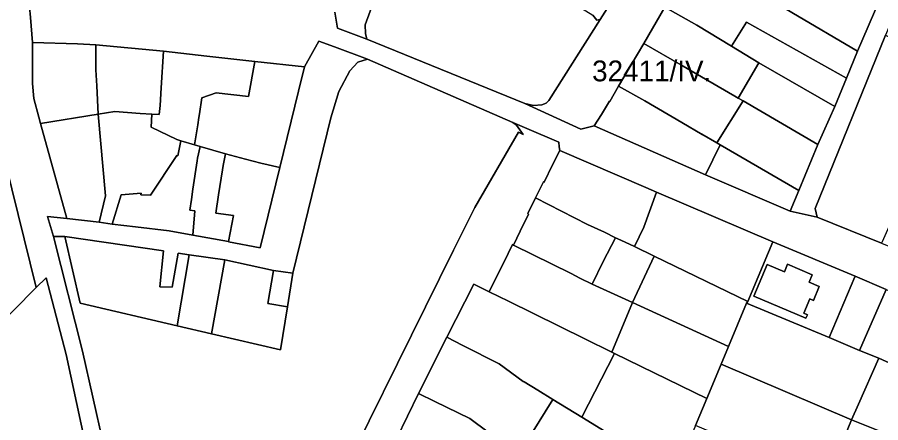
# Model space of a CAD drawing. Extents: x -545779 to -541342, y -1153413 to -1149956.
# Drawn here: x -544066.7 to -543859.4, y -1151540.7 to -1151443.3 of the extents above; entities that cross this region are included whole.
import ezdxf

# ---------------------------------------------------------------- set-up
doc = ezdxf.new("R2010")
doc.units = 0
for name, color, linetype in [('95590013', 7, 'Continuous'), ('95640013', 7, 'Continuous'), ('95660013', 7, 'Continuous')]:
    doc.layers.add(name, color=color, linetype=linetype)

msp = doc.modelspace()

# ---------------------------------------------------------------- linework, layer by layer
at = {"layer": '95590013'}
for points in [[(-543864.92, -1151451.44), (-543880.7, -1151442.14), (-543882.45, -1151441.11), (-543879.44, -1151435.98), (-543880.89, -1151435.09), (-543879.44, -1151432.74), (-543877.14, -1151429.03), (-543877.1, -1151429.06), (-543859.58, -1151438.92)], [(-543867.57, -1151457.91), (-543870.36, -1151464.7), (-543888.64, -1151454.25), (-543895.17, -1151450.23), (-543891.62, -1151444.46)], [(-543858.23, -1151447.61), (-543845.56, -1151454.17), (-543851.61, -1151466.63), (-543856.46, -1151476.49), (-543850.95, -1151479.09), (-543859.02, -1151497.28), (-543859.15, -1151497.57), (-543874.59, -1151491.33), (-543875.12, -1151489.24)], [(-543888.64, -1151454.25), (-543870.36, -1151464.7), (-543874.49, -1151473.89), (-543892.43, -1151463.38), (-543893.59, -1151462.7)], [(-543898.7, -1151473.44), (-543892.43, -1151463.38), (-543874.49, -1151473.89), (-543879.06, -1151484.91), (-543897.9, -1151473.91)], [(-544062.12, -1151508.24), (-544078.49, -1151524.76), (-544088.04, -1151515.33), (-544106.01, -1151497.58), (-544109.75, -1151501.5), (-544111.49, -1151503.24), (-544116.04, -1151498.64), (-544108.55, -1151493.23), (-544095.64, -1151483.9), (-544089.36, -1151479.12), (-544081.32, -1151473.35), (-544072.41, -1151466.98)], [(-544045.51, -1151486.18), (-544046.99, -1151492.53), (-544054.77, -1151491.65), (-544061.07, -1151468.84), (-544047.29, -1151466.58)], [(-543901.43, -1151481.18), (-543897.9, -1151473.91), (-543879.06, -1151484.91), (-543881.14, -1151489.91)], [(-543918.52, -1151498.37), (-543916.28, -1151493.68), (-543913.17, -1151485.27), (-543885.28, -1151497.22), (-543891.31, -1151511.55), (-543913.8, -1151500.66)], [(-543918.93, -1151511.86), (-543928.68, -1151507.38), (-543926.04, -1151501.94), (-543923.02, -1151496.25), (-543921.76, -1151496.84), (-543918.52, -1151498.37), (-543913.8, -1151500.66)], [(-543891.31, -1151511.55), (-543885.28, -1151497.22), (-543865.54, -1151505.52), (-543865.61, -1151505.69), (-543871.74, -1151520.26), (-543891.57, -1151511.95)], [(-543895.94, -1151522.41), (-543918.93, -1151511.86), (-543913.8, -1151500.66), (-543891.31, -1151511.55), (-543891.57, -1151511.95)], [(-543876.57, -1151506.93), (-543875.82, -1151505.2), (-543881.71, -1151502.65), (-543882.48, -1151504.43), (-543886.63, -1151502.71), (-543889.83, -1151510.27), (-543877.33, -1151515.58), (-543876.98, -1151514.76), (-543877.81, -1151514.41), (-543876.35, -1151510.96), (-543875.51, -1151511.31), (-543874.11, -1151508)], [(-543864.44, -1151523.32), (-543871.74, -1151520.26), (-543865.61, -1151505.69), (-543865.54, -1151505.52), (-543858.06, -1151508.67)], [(-543897.69, -1151526.61), (-543901.15, -1151534.9), (-543923.3, -1151524.04), (-543923.95, -1151523.73), (-543918.93, -1151511.86), (-543895.94, -1151522.41)], [(-543864.44, -1151523.32), (-543859.86, -1151525.24), (-543864.71, -1151536.29), (-543866.35, -1151540.03), (-543897.69, -1151526.61), (-543895.94, -1151522.41), (-543891.57, -1151511.95), (-543871.74, -1151520.26)], [(-543908.74, -1151553.12), (-543931.16, -1151539.37), (-543923.3, -1151524.04), (-543901.15, -1151534.9), (-543903.86, -1151541.41)], [(-543866.35, -1151540.03), (-543868.11, -1151544.31), (-543866.19, -1151545.1), (-543868.96, -1151552.11), (-543870.4, -1151555.33), (-543873.85, -1151554.05), (-543903.86, -1151541.41), (-543901.15, -1151534.9), (-543897.69, -1151526.61)], [(-543931.16, -1151539.37), (-543908.74, -1151553.12), (-543909.99, -1151556.12), (-543915.76, -1151570.84), (-543916.2, -1151571.83), (-543944.42, -1151550.28), (-543945.42, -1151549.52), (-543946.47, -1151548.7), (-543938.07, -1151535.13)]]:
    msp.add_lwpolyline(points, close=True, dxfattribs=at)
at = {"layer": '95640013'}
for points in [[(-543846.73, -1151420.31), (-543858.23, -1151447.61), (-543875.12, -1151489.24), (-543874.59, -1151491.33), (-543881.14, -1151489.91), (-543879.06, -1151484.91), (-543874.49, -1151473.89), (-543870.36, -1151464.7), (-543867.57, -1151457.91), (-543864.92, -1151451.44), (-543859.58, -1151438.92)], [(-543978.45, -1151432.12), (-543983.11, -1151445.08), (-543983.05, -1151447.16), (-543982.78, -1151448.51), (-543989.81, -1151445.87), (-543990.4, -1151442.09)], [(-543911.19, -1151440.86), (-543916.27, -1151449.57), (-543922.31, -1151459.86), (-543924.4, -1151463.5), (-543924.51, -1151463.43), (-543926.44, -1151466.65), (-543928.13, -1151469.39), (-543931.36, -1151470.13), (-543944.8, -1151463.97), (-543942.7, -1151464.52), (-543940.7, -1151464.35), (-543939.69, -1151463.92), (-543939.06, -1151463.27), (-543926.7, -1151443.82), (-543923.74, -1151439.11)], [(-543923.74, -1151439.11), (-543926.7, -1151443.82), (-543927.51, -1151443.98), (-543928.47, -1151442.75)], [(-544063.73, -1151440.78), (-544063.52, -1151443.31), (-544063.02, -1151449.37), (-544062.99, -1151459.16), (-544062.69, -1151462.83), (-544061.48, -1151467.29), (-544061.07, -1151468.84), (-544054.77, -1151491.65), (-544059.38, -1151491.13), (-544058, -1151496), (-544051.04, -1151523.5), (-544043.56, -1151556.66), (-544036.62, -1151600.3), (-544039.55, -1151601.25), (-544047.71, -1151557.78), (-544054.9, -1151524.32), (-544059.76, -1151505.86), (-544062.12, -1151508.24), (-544072.41, -1151466.98)], [(-543858.06, -1151508.67), (-543865.54, -1151505.52), (-543885.28, -1151497.22), (-543913.17, -1151485.27), (-543915.75, -1151484.17), (-543936.43, -1151475.31), (-543936.53, -1151474.42), (-543936.66, -1151473.29), (-543944.36, -1151470.02), (-543947.72, -1151468.6), (-543982.6, -1151453.35), (-543990.51, -1151450.41), (-543994.29, -1151449.01), (-543997.75, -1151455.17), (-544009.64, -1151453.87), (-544021.2, -1151452.61), (-544031.57, -1151451.4), (-544047.8, -1151449.94), (-544052.19, -1151449.68), (-544063.02, -1151449.37), (-544063.52, -1151443.31), (-544063.73, -1151440.78)], [(-543990.4, -1151442.09), (-543989.81, -1151445.87), (-543982.78, -1151448.51), (-543944.8, -1151463.97), (-543931.36, -1151470.13), (-543928.13, -1151469.39), (-543901.43, -1151481.18), (-543881.14, -1151489.91), (-543874.59, -1151491.33), (-543859.15, -1151497.57), (-543843.54, -1151503.88), (-543840.21, -1151506.13), (-543832.04, -1151511.64), (-543794.09, -1151527.78), (-543715.42, -1151558.92)], [(-544043.56, -1151556.66), (-544051.04, -1151523.5), (-544058, -1151496), (-544055.23, -1151495.99), (-544051.57, -1151511.96), (-544028.31, -1151517.41), (-544020.04, -1151519.34), (-544003.49, -1151523.2), (-544001.76, -1151512.89), (-544000.5, -1151504.81), (-543991.36, -1151467.47), (-543989.48, -1151461.15), (-543986.86, -1151456.12), (-543984.94, -1151454.08), (-543982.6, -1151453.35), (-543947.72, -1151468.6), (-543946.8, -1151469.22), (-543945.23, -1151471.42), (-543946.34, -1151470.89), (-543956.79, -1151488.97), (-543961.96, -1151499.28), (-543995.62, -1151567.47)], [(-543995.62, -1151567.47), (-543961.96, -1151499.28), (-543956.79, -1151488.97), (-543946.34, -1151470.89), (-543945.23, -1151471.42), (-543946.8, -1151469.22), (-543947.72, -1151468.6), (-543944.36, -1151470.02), (-543936.66, -1151473.29), (-543936.53, -1151474.42), (-543936.43, -1151475.31), (-543938.15, -1151478.77), (-543940.18, -1151482.9), (-543940.36, -1151482.81), (-543942.23, -1151486.67), (-543944.1, -1151490.46), (-543943.93, -1151490.56), (-543945.93, -1151494.68), (-543947.56, -1151498.02), (-543947.76, -1151497.92), (-543948.81, -1151500.05), (-543953.35, -1151509.25), (-543957.09, -1151507.39), (-543963.55, -1151520.17), (-543970.31, -1151533.73), (-543975.66, -1151544.55)]]:
    msp.add_lwpolyline(points, dxfattribs=at)
for points in [[(-543970.28, -1151425.13), (-543967.37, -1151424.91), (-543964.36, -1151425.33), (-543953.41, -1151429.63), (-543944.83, -1151433.37), (-543937.67, -1151436.98), (-543928.47, -1151442.75), (-543927.51, -1151443.98), (-543926.7, -1151443.82), (-543939.06, -1151463.27), (-543939.69, -1151463.92), (-543940.7, -1151464.35), (-543942.7, -1151464.52), (-543944.8, -1151463.97), (-543982.78, -1151448.51), (-543983.05, -1151447.16), (-543983.11, -1151445.08), (-543978.45, -1151432.12), (-543977.23, -1151429.86), (-543975.52, -1151427.97), (-543973.04, -1151426.23)], [(-543867.57, -1151457.91), (-543891.62, -1151444.46), (-543895.17, -1151450.23), (-543903.53, -1151445.2), (-543911.19, -1151440.86), (-543903.86, -1151428.52), (-543897.77, -1151432.12), (-543894.4, -1151434.11), (-543886.29, -1151438.86), (-543882.45, -1151441.11), (-543880.7, -1151442.14), (-543864.92, -1151451.44)], [(-543916.27, -1151449.57), (-543911.19, -1151440.86), (-543903.53, -1151445.2), (-543895.17, -1151450.23), (-543888.64, -1151454.25), (-543893.59, -1151462.7), (-543894.37, -1151462.25), (-543907.37, -1151454.71)], [(-544047.84, -1151455.49), (-544047.84, -1151455.94), (-544047.6, -1151459.75), (-544047.29, -1151466.58), (-544061.07, -1151468.84), (-544061.48, -1151467.29), (-544062.69, -1151462.83), (-544062.99, -1151459.16), (-544063.02, -1151449.37), (-544052.19, -1151449.68), (-544047.8, -1151449.94)], [(-543991.36, -1151467.47), (-544000.5, -1151504.81), (-544005.16, -1151504.11), (-544016.83, -1151501.56), (-544025.41, -1151500.33), (-544028.08, -1151499.94), (-544029.47, -1151508.13), (-544032.45, -1151508.02), (-544031.57, -1151499.43), (-544055.23, -1151495.99), (-544058, -1151496), (-544059.38, -1151491.13), (-544054.77, -1151491.65), (-544046.99, -1151492.53), (-544043.88, -1151492.98), (-544038.28, -1151493.63), (-544030.21, -1151494.58), (-544024.53, -1151495.63), (-544015.96, -1151497.13), (-544015.99, -1151497.28), (-544008.37, -1151498.72), (-544003.61, -1151479.41), (-543999.17, -1151461.06), (-543997.75, -1151455.17), (-543994.29, -1151449.01), (-543990.51, -1151450.41), (-543982.6, -1151453.35), (-543984.94, -1151454.08), (-543986.86, -1151456.12), (-543989.48, -1151461.15)], [(-544047.29, -1151466.58), (-544047.6, -1151459.75), (-544047.84, -1151455.94), (-544047.84, -1151455.49), (-544047.8, -1151449.94), (-544031.57, -1151451.4), (-544032.1, -1151460.22), (-544032.4, -1151464.45), (-544032.58, -1151466.67), (-544034.35, -1151466.56), (-544037.13, -1151466.44), (-544043.27, -1151465.9)], [(-544032.4, -1151464.45), (-544032.1, -1151460.22), (-544031.57, -1151451.4), (-544021.2, -1151452.61), (-544009.64, -1151453.87), (-544011.14, -1151462.34), (-544018.93, -1151461.43), (-544022.38, -1151462.66), (-544022.94, -1151466.45), (-544023.09, -1151467.36), (-544023.36, -1151469.1), (-544024.13, -1151473.93), (-544027.37, -1151472.95), (-544028.33, -1151472.66), (-544034.55, -1151469.68), (-544034.35, -1151466.56), (-544032.58, -1151466.67)], [(-543916.04, -1151463.34), (-543922.31, -1151459.86), (-543916.27, -1151449.57), (-543907.37, -1151454.71), (-543894.37, -1151462.25), (-543893.59, -1151462.7), (-543892.43, -1151463.38), (-543898.7, -1151473.44), (-543902.28, -1151471.39), (-543902.26, -1151471.47), (-543907.14, -1151468.55)], [(-544003.61, -1151479.41), (-544008.17, -1151478.35), (-544011.84, -1151477.38), (-544016.68, -1151476.1), (-544022.79, -1151474.34), (-544024.13, -1151473.93), (-544023.36, -1151469.1), (-544023.09, -1151467.36), (-544022.94, -1151466.45), (-544022.38, -1151462.66), (-544018.93, -1151461.43), (-544011.14, -1151462.34), (-544009.64, -1151453.87), (-543997.75, -1151455.17), (-543999.17, -1151461.06)], [(-543922.31, -1151459.86), (-543916.04, -1151463.34), (-543907.14, -1151468.55), (-543902.26, -1151471.47), (-543902.28, -1151471.39), (-543898.7, -1151473.44), (-543897.9, -1151473.91), (-543901.43, -1151481.18), (-543928.13, -1151469.39), (-543926.44, -1151466.65), (-543924.51, -1151463.43), (-543924.4, -1151463.5)], [(-544047.29, -1151466.58), (-544043.27, -1151465.9), (-544037.13, -1151466.44), (-544034.35, -1151466.56), (-544034.55, -1151469.68), (-544028.33, -1151472.66), (-544027.37, -1151472.95), (-544028.1, -1151476.58), (-544028.39, -1151476.49), (-544034.71, -1151486.03), (-544036.97, -1151485.98), (-544036.94, -1151485.54), (-544041.74, -1151485.92), (-544043.88, -1151492.98), (-544046.99, -1151492.53), (-544045.51, -1151486.18)], [(-544028.39, -1151476.49), (-544028.1, -1151476.58), (-544027.37, -1151472.95), (-544024.13, -1151473.93), (-544022.79, -1151474.34), (-544023.37, -1151477.16), (-544023.49, -1151477.75), (-544024.52, -1151484.61), (-544024.85, -1151487.04), (-544025.23, -1151489.66), (-544024.03, -1151489.81), (-544024.53, -1151495.63), (-544030.21, -1151494.58), (-544038.28, -1151493.63), (-544043.88, -1151492.98), (-544041.74, -1151485.92), (-544036.94, -1151485.54), (-544036.97, -1151485.98), (-544034.71, -1151486.03)], [(-544023.49, -1151477.75), (-544023.37, -1151477.16), (-544022.79, -1151474.34), (-544016.68, -1151476.1), (-544017.23, -1151478.94), (-544017.42, -1151479.92), (-544018.4, -1151485.96), (-544019, -1151490.39), (-544014.79, -1151490.89), (-544015.96, -1151497.13), (-544024.53, -1151495.63), (-544024.03, -1151489.81), (-544025.23, -1151489.66), (-544024.85, -1151487.04), (-544024.52, -1151484.61)], [(-544003.61, -1151479.41), (-544008.37, -1151498.72), (-544015.99, -1151497.28), (-544015.96, -1151497.13), (-544014.79, -1151490.89), (-544019, -1151490.39), (-544018.4, -1151485.96), (-544017.42, -1151479.92), (-544017.23, -1151478.94), (-544016.68, -1151476.1), (-544011.84, -1151477.38), (-544008.17, -1151478.35)], [(-543918.52, -1151498.37), (-543921.76, -1151496.84), (-543923.02, -1151496.25), (-543925.69, -1151494.93), (-543929.79, -1151493.06), (-543942.23, -1151486.67), (-543940.36, -1151482.81), (-543940.18, -1151482.9), (-543938.15, -1151478.77), (-543936.43, -1151475.31), (-543915.75, -1151484.17), (-543913.17, -1151485.27), (-543916.28, -1151493.68)], [(-543925.69, -1151494.93), (-543923.02, -1151496.25), (-543926.04, -1151501.94), (-543928.68, -1151507.38), (-543931.58, -1151506.01), (-543933.65, -1151504.89), (-543947.56, -1151498.02), (-543945.93, -1151494.68), (-543943.93, -1151490.56), (-543944.1, -1151490.46), (-543942.23, -1151486.67), (-543929.79, -1151493.06)], [(-544025.41, -1151500.33), (-544028.31, -1151517.41), (-544051.57, -1151511.96), (-544055.23, -1151495.99), (-544031.57, -1151499.43), (-544032.45, -1151508.02), (-544029.47, -1151508.13), (-544028.08, -1151499.94)], [(-543948.81, -1151500.05), (-543947.76, -1151497.92), (-543947.56, -1151498.02), (-543933.65, -1151504.89), (-543931.58, -1151506.01), (-543928.68, -1151507.38), (-543918.93, -1151511.86), (-543923.95, -1151523.73), (-543930.44, -1151520.54), (-543948.76, -1151511.51), (-543953.35, -1151509.25)], [(-544025.41, -1151500.33), (-544016.83, -1151501.56), (-544020.04, -1151519.34), (-544028.31, -1151517.41)], [(-544016.83, -1151501.56), (-544005.16, -1151504.11), (-544006.48, -1151512.09), (-544001.76, -1151512.89), (-544003.49, -1151523.2), (-544020.04, -1151519.34)], [(-543882.48, -1151504.43), (-543881.71, -1151502.65), (-543875.82, -1151505.2), (-543876.57, -1151506.93), (-543874.11, -1151508), (-543875.51, -1151511.31), (-543876.35, -1151510.96), (-543877.81, -1151514.41), (-543876.98, -1151514.76), (-543877.33, -1151515.58), (-543889.83, -1151510.27), (-543886.63, -1151502.71)], [(-544006.48, -1151512.09), (-544005.16, -1151504.11), (-544000.5, -1151504.81), (-544001.76, -1151512.89)], [(-544052.07, -1151590.59), (-544055.2, -1151593.01), (-544067.38, -1151579.03), (-544097.69, -1151549.46), (-544091.86, -1151543.49), (-544085.85, -1151537.43), (-544087.53, -1151535.79), (-544085.47, -1151532.93), (-544082.3, -1151528.55), (-544078.49, -1151524.76), (-544062.12, -1151508.24), (-544059.76, -1151505.86), (-544054.9, -1151524.32), (-544047.71, -1151557.78), (-544039.55, -1151601.25), (-544044.49, -1151593.92), (-544045.27, -1151592.88), (-544048.82, -1151588.16)], [(-543945.22, -1151530.84), (-543950.96, -1151526.54), (-543959.73, -1151522.18), (-543963.55, -1151520.17), (-543957.09, -1151507.39), (-543953.35, -1151509.25), (-543948.76, -1151511.51), (-543930.44, -1151520.54), (-543923.95, -1151523.73), (-543923.3, -1151524.04), (-543931.16, -1151539.37), (-543938.07, -1151535.13), (-543941.73, -1151532.88), (-543944.98, -1151530.92)], [(-543838.07, -1151534.67), (-543847.19, -1151530.69), (-543851.4, -1151528.92), (-543858.03, -1151526.01), (-543859.86, -1151525.24), (-543864.44, -1151523.32), (-543858.06, -1151508.67), (-543831.79, -1151519.89), (-543830.36, -1151521.75), (-543830.21, -1151524.01), (-543835.21, -1151535.82)], [(-543952.58, -1151543.91), (-543953.65, -1151543.02), (-543957.99, -1151539.67), (-543966.43, -1151535.63), (-543970.31, -1151533.73), (-543963.55, -1151520.17), (-543959.73, -1151522.18), (-543950.96, -1151526.54), (-543945.22, -1151530.84), (-543944.98, -1151530.92), (-543941.73, -1151532.88), (-543938.07, -1151535.13), (-543946.47, -1151548.7)], [(-543841.38, -1151550.49), (-543857.2, -1151543.7), (-543866.35, -1151540.03), (-543864.71, -1151536.29), (-543859.86, -1151525.24), (-543858.03, -1151526.01), (-543851.4, -1151528.92), (-543847.19, -1151530.69), (-543838.07, -1151534.67), (-543835.21, -1151535.82)], [(-543953.05, -1151557.98), (-543959.62, -1151553.01), (-543963.07, -1151550.38), (-543975.66, -1151544.55), (-543970.31, -1151533.73), (-543966.43, -1151535.63), (-543957.99, -1151539.67), (-543953.65, -1151543.02), (-543952.58, -1151543.91), (-543946.47, -1151548.7), (-543945.42, -1151549.52), (-543944.42, -1151550.28), (-543951, -1151559.52)], [(-543870.4, -1151555.33), (-543868.96, -1151552.11), (-543866.19, -1151545.1), (-543868.11, -1151544.31), (-543866.35, -1151540.03), (-543857.2, -1151543.7), (-543841.38, -1151550.49), (-543847.67, -1151565.16), (-543850.54, -1151563.92), (-543859.52, -1151560.17), (-543859.85, -1151560.04), (-543862.38, -1151558.93), (-543863.2, -1151558.54)]]:
    msp.add_lwpolyline(points, close=True, dxfattribs=at)

# ---------------------------------------------------------------- texts
at = {"layer": '95660013'}
msp.add_text('32411/IV.', height=5, rotation=0, dxfattribs=at).set_placement((-543928.66, -1151458.675))

doc.saveas('drawing.dxf')
